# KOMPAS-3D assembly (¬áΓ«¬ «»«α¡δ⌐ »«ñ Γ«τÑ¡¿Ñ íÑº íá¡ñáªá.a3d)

Referenced files in D:\МОДЕЛЬ ТАНКА Т90\ДЕТАЛИ\ХОДОВАЯ\Каток опорный с балансиром\: каток опорный без бандажа.m3d
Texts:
  Сборка каток опорный под точение без бандажа
  stalker61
